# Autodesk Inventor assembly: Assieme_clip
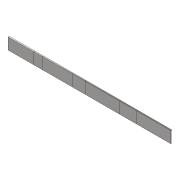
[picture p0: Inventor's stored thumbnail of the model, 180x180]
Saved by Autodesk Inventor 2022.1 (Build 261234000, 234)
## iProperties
Created: 2022-02
Part Number: Assieme_clip
Document SubType Name: Assembly
Designer: i911900
Author: i911900
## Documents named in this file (3)
- C:\Users\i911900\Desktop\inventor\filo_piegatura_tranciatura2\Assieme_clip.iam
- C:\Users\i911900\Desktop\inventor\filo_piegatura_tranciatura2\filo_clip_2mm.ipt
- C:\Users\i911900\Desktop\inventor\filo_piegatura_tranciatura2\incastro.ipt
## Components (2 placed, 2 different names)
1. filo_clip_2mm:1 — Rigido:1
2. incastro:1 — Rigido:1
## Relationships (1: WeldJoint 1)
- Rigido:1 [WeldJoint]: filo_clip_2mm:1 ↔ incastro:1
